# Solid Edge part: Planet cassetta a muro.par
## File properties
Title: Planet cassetta a muro
Author: DESYS
Template: Normal.par
Last saved by: s.pallini
Revision: 36
Application: Solid Edge
Tipo di contenuto documento: 0
Precisione: 0,99
Document Number: 8107
Revision: 0
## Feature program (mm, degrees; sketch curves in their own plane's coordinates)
sketch for "ExtrudedProtrusion_1" plane through (0, 0, 0) normal (0, -1, 0) x-axis (1, 0, 0)
  line (-190, -53.3265) -> (190, -53.3265)
  line (190, -53.3265) -> (190, 886.6735)
  line (190, 886.6735) -> (-190, 886.6735)
  line (-190, -53.3265) -> (-190, 886.6735)
  dimension (linear) = 190
  dimension (linear) = 190
extrude "ExtrudedProtrusion_1" add finite 145 along -normal
sketch for "ExtrudedCutout_1" plane through (0, 145, 421.6735) normal (0, 1, 0) x-axis (-1, 0, 0)
  line (-155, 450) -> (-155, -430)
  line (-155, -430) -> (155, -430)
  line (155, 450) -> (155, -430)
  line (-155, 450) -> (155, 450)
extrude "ExtrudedCutout_1" cut finite 120 along -normal
sketch for "unnamed Cutout 1" plane through (0, 25, 441.6735) normal (0, 1, 0) x-axis (-1, 0, 0)
  line (-82.5, -450) -> (-82.5, -200)
  line (82.5, -200) -> (82.5, -450)
  line (82.5, -450) -> (-82.5, -450)
  dimension (linear) = 82.5
  dimension (linear) = 82.5
extrude "unnamed Cutout 1" cut through along -normal
sketch for "unnamed Cutout 2" plane through (0, 70, -53.3265) normal (0, 0, -1) x-axis (-1, 0, 0)
  line (-110, -40) -> (110, -40)
  arc centre (110, -20) radius 20 from (110, -40) to (130, -20) ccw
  line (130, -20) -> (130, 20)
  arc centre (110, 20) radius 20 from (130, 20) to (110, 40) ccw
  line (110, 40) -> (-110, 40)
  arc centre (-110, 20) radius 20 from (-130, 20) to (-110, 40) cw
  line (-130, 20) -> (-130, -20)
  arc centre (-110, -20) radius 20 from (-130, -20) to (-110, -40) ccw
  dimension (linear) = 110
  dimension (linear) = 130
extrude "unnamed Cutout 2" cut through along -normal
sketch for "Foro_1" plane through (0, 0, 0) normal (0, 0, 1) x-axis (1, 0, 0)
  hole centre (0, 95) bore radius 20
hole "Foro_1" diameter 40 through
sketch for "ExtrudedCutout_4" #1 plane through (0, 145, 421.6735) normal (0, 1, 0) x-axis (-1, 0, 0)
  line (160, 434.7992) -> (160, -442.9749)
  arc centre (170, -442.9749) radius 10 from (179.9705, -443.7424) to (160, -442.9749) cw
  line (169.9752, 435.2962) -> (179.9705, -443.7424)
  arc centre (165, 434.7992) radius 5 from (160, 434.7992) to (169.9752, 435.2962) cw
sketch for "ExtrudedCutout_4" #2 plane through (0, 145, 421.6735) normal (0, 1, 0) x-axis (-1, 0, 0)
  line (-122.5, -470) -> (122.5, -470)
  arc centre (122.5, -465) radius 5 from (122.5, -470) to (127.5, -465) ccw
  line (127.5, -465) -> (127.5, -440)
  arc centre (122.5, -440) radius 5 from (122.5, -435) to (127.5, -440) cw
  line (122.5, -435) -> (-122.5, -435)
  arc centre (-122.5, -440) radius 5 from (-122.5, -435) to (-127.5, -440) ccw
  line (-127.5, -440) -> (-127.5, -465)
  arc centre (-122.5, -465) radius 5 from (-127.5, -465) to (-122.5, -470) ccw
sketch for "ExtrudedCutout_4" #3 plane through (0, 145, 421.6735) normal (0, 1, 0) x-axis (-1, 0, 0)
  line (-160, 434.7992) -> (-160, -442.9749)
  arc centre (-170, -442.9749) radius 10 from (-179.9705, -443.7424) to (-160, -442.9749) ccw
  line (-169.9752, 435.2962) -> (-179.9705, -443.7424)
  arc centre (-165, 434.7992) radius 5 from (-160, 434.7992) to (-169.9752, 435.2962) ccw
extrude "ExtrudedCutout_4" cut finite 8 along -normal
sketch for "ExtrudedProtrusion_2" plane through (0, 25, 441.6735) normal (0, 1, 0) x-axis (0, 0, 1)
  line (-200, 82.5) -> (-430, 82.5)
  line (-430, 92.5) -> (-430, 82.5)
  line (-200, 92.5) -> (-430, 92.5)
  arc centre (-200, 0) radius 92.5 from (-200, -92.5) to (-200, 92.5) ccw
  line (-430, -92.5) -> (-200, -92.5)
  line (-430, -82.5) -> (-430, -92.5)
  line (-200, -82.5) -> (-430, -82.5)
  arc centre (-200, 0) radius 82.5 from (-200, -82.5) to (-200, 82.5) ccw
extrude "ExtrudedProtrusion_2" add finite 10 along +normal
fillet "Rotondo_1" radius 5
draft "Draft_1"  Angles1 = 10 deg
sketch for "unnamed Cutout 3" plane through (0, 72.5, 886.6735) normal (0, 0, 1) x-axis (-1, 0, 0)
extrude "unnamed Cutout 3" cut through along -normal
fillet "Rotondo_6" radius 10
fillet "Rotondo_7" radius 5
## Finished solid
Body 1: solid body, 107 faces, 250 edges, 142 vertices.
  Faces by surface: cylinder 49, plane 33, torus 21, sphere 4
  Edges by curve: line 133, circle 108, intersection 5, ellipse 4
Bounding box of the edges (mm; curved faces can reach further): 380.000 x 145.000 x 940.000, from (-190, 0, -53.3265) to (190, 145, 886.6735).
Cylindrical faces by radius (mm): R5 x33, R10 x7, R20 x5, R55 x2, R82.5 x1, R92.5 x1
Toroidal faces (ring radius, tube radius in mm): R10 r5 x6, R15 r5 x2, R25 r5 x8, R50 r5 x4, R87.5 r5 x1
Spherical faces by radius (mm): R5 x2, R10 x2
Planar faces by outward normal: +x 6, +y 6, +z 4, -x 6, -y 2, -z 5, oblique 4
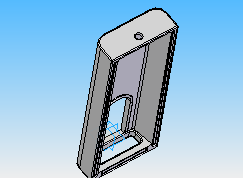
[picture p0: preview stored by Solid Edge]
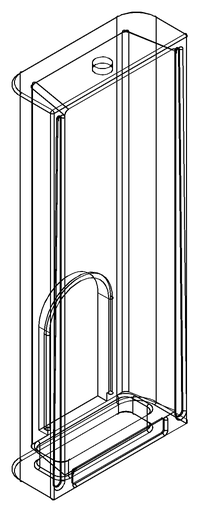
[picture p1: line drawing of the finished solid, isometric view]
